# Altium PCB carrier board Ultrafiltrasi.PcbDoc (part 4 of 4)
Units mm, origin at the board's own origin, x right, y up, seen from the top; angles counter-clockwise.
Board outline 196.34 x 220.85 mm, 2 copper layers (Top Layer, Bottom Layer); 114 components, 209 nets, 667 pads, 70 vias.
Unrouted connection lines stored in the file: 5.
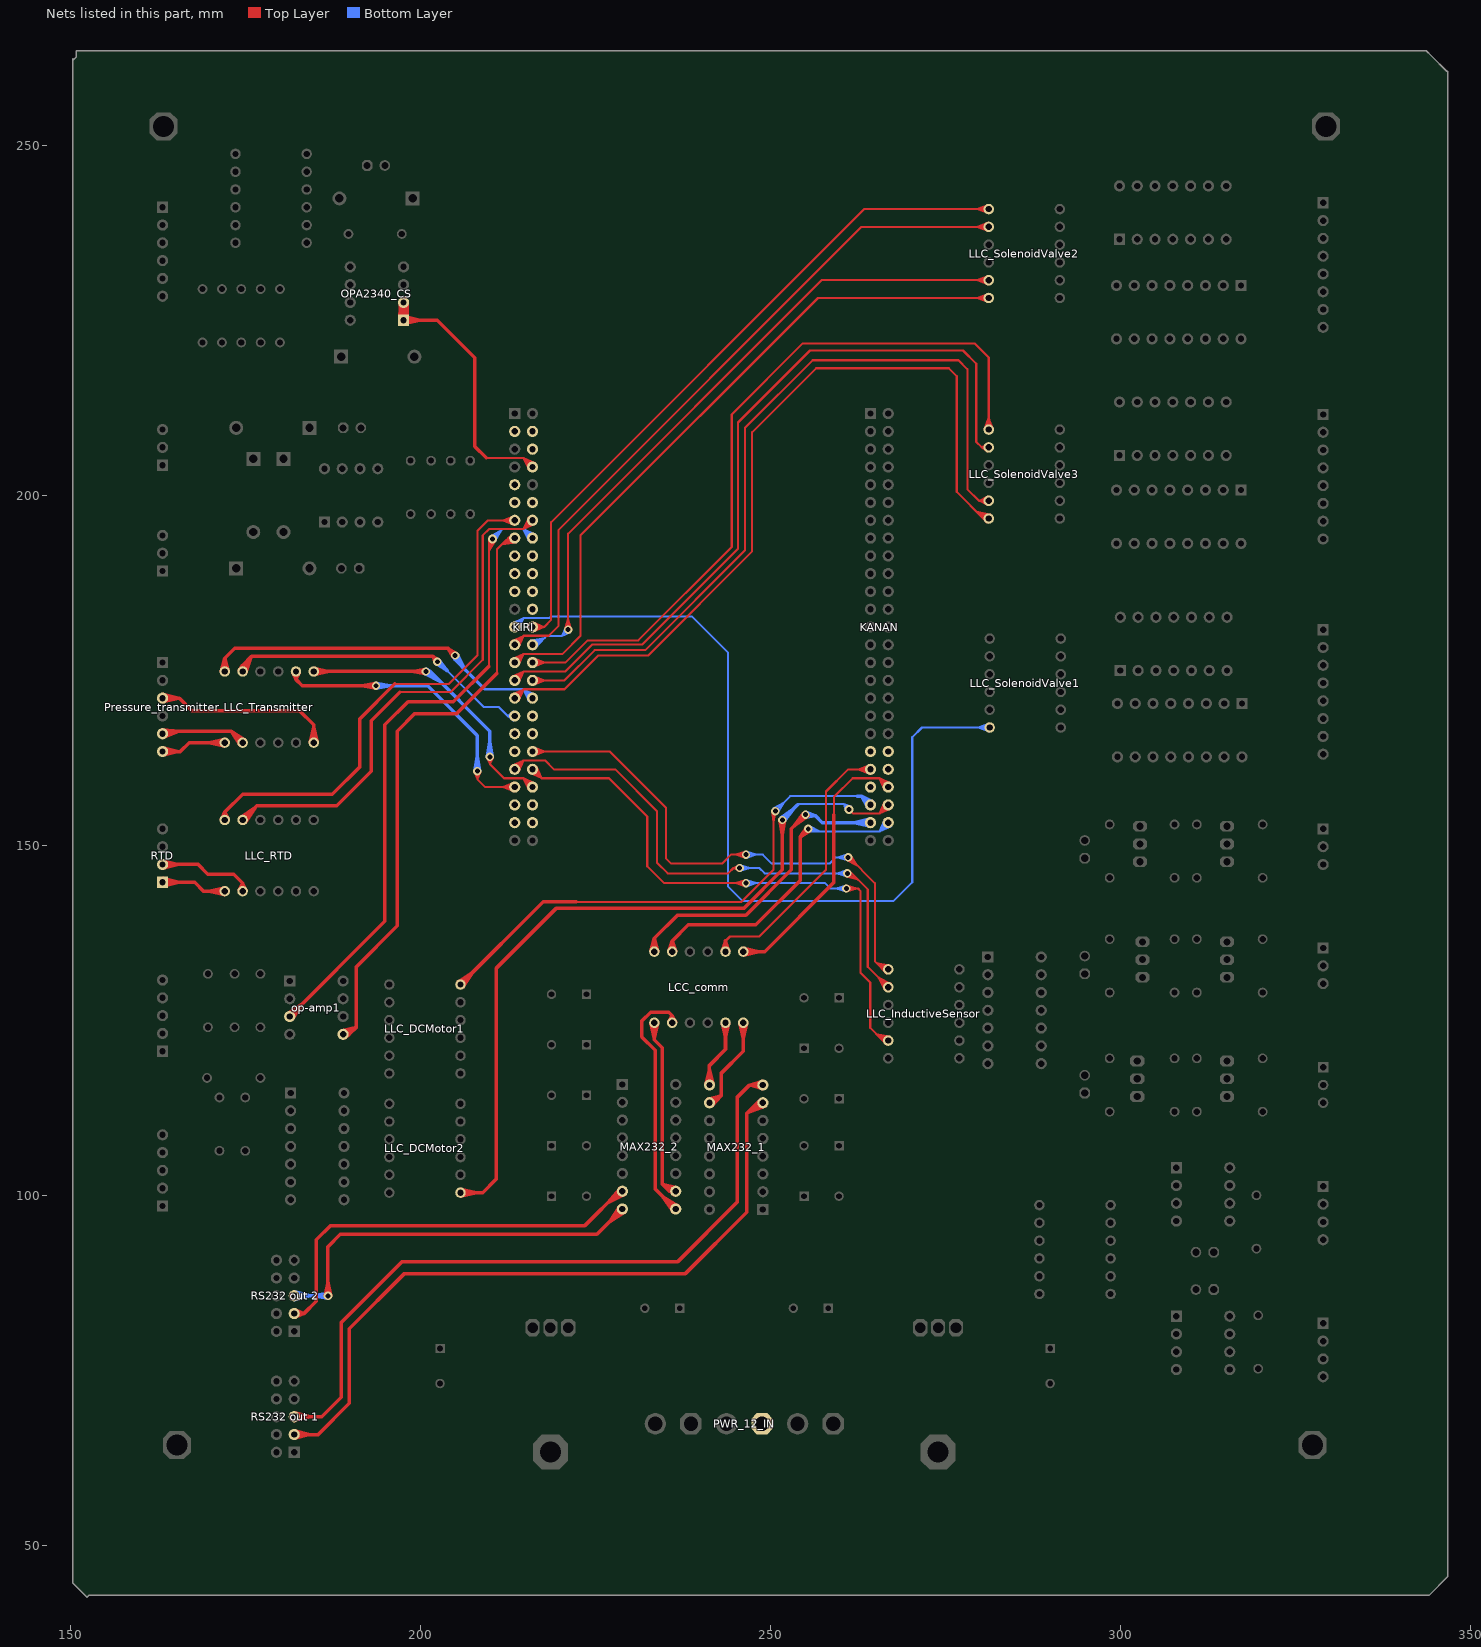
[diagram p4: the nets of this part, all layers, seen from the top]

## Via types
v1: diameter 1.2, hole 0.711, Top Layer to Bottom Layer, 26 vias
v2: diameter 1.27, hole 0.711, Top Layer to Bottom Layer, 24 vias
v3: diameter 1.2, hole 0.7, Top Layer to Bottom Layer, 19 vias
v4: diameter 1.5, hole 0.8, Top Layer to Bottom Layer, 1 vias

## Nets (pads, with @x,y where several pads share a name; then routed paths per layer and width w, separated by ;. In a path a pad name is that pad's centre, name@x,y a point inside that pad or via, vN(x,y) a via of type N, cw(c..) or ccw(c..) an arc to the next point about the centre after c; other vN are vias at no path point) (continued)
NetKANAN_39: KANAN.39
NetKANAN_40: KANAN.40
NetKANAN_41: KANAN.41 LCC_comm.P$2 | length 48.8
  Top Layer w0.3: 243.586,136.398 244.221,137.033 248.412,137.033 257.937,146.558 257.937,157.734 261.112,160.909 KANAN.41@264.287,160.909 ; KANAN.41@264.163,160.271 262.587,160.909 ; KANAN.41@264.163,161.547 262.587,160.909 ; KANAN.41@264.251,160.561 262.587,160.909 ; KANAN.41@264.251,161.257 262.587,160.909
  Top Layer w0.5: LCC_comm.P$2@243.093,134.956 243.586,136.398 ; LCC_comm.P$2@243.586,134.874 243.586,136.398 ; LCC_comm.P$2@244.079,134.956 243.586,136.398
NetKANAN_42: KANAN.42
NetKANAN_43: KANAN.43
NetKANAN_44: KANAN.44 LCC_comm.P$1 | length 52.1
  Top Layer w0.3: 259.08,154.432 259.08,156.972 261.747,159.639 265.557,159.639 ; KANAN.44@266.292,158 265.557,159.639 ; KANAN.44@266.557,158.147 265.557,159.639 ; KANAN.44@267.049,158.639 265.557,159.639 ; KANAN.44@267.196,158.904 265.557,159.639 ; 265.557,159.639 KANAN.44@266.827,158.369 265.557,159.639
  Top Layer w0.5: LCC_comm.P$1@246.126,134.874 249.174,134.874 259.08,144.78 259.08,154.432 ; LCC_comm.P$1@246.182,134.377 248.376,134.874 LCC_comm.P$1@246.182,135.371
NetKANAN_45: KANAN.45 LLC_DCMotor1.P$6 | length 92.1
  Top Layer w0.3: 222.25,141.986 245.872,141.986 250.444,146.558 250.444,154.686 v1(250.698,154.94) 250.444,153.367 v1@250.248,154.948
  Top Layer w0.5: LLC_DCMotor1.P$6@205.423,130.561 207.551,131.986 LLC_DCMotor1.P$6@206.126,129.858 ; LLC_DCMotor1.P$6@205.74,130.175 217.551,141.986 222.25,141.986
  Bottom Layer w0.3: v1@250.423,155.296 251.934,156.176 v1@251.054,154.665 ; v1(250.698,154.94) 252.837,157.079 262.382,157.079
  Bottom Layer w0.5: 262.382,157.079 263.037,157.079 ; KANAN.45@263.842,155.505 263.037,157.079 ; KANAN.45@264.611,156.274 263.037,157.079 ; 263.037,157.079 KANAN.45@264.287,155.829 263.037,157.079
NetKANAN_46: KANAN.46 LLC_DCMotor2.P$1 | length 135.6
  Top Layer w0.3: v2(261.239,155.194) 261.854,154.579 265.577,154.579 ; KANAN.46@266.291,156.196 265.577,154.579 ; KANAN.46@266.556,156.051 265.577,154.579 ; KANAN.46@267.049,155.558 265.577,154.579 ; KANAN.46@267.194,155.293 265.577,154.579 ; 265.577,154.579 KANAN.46@266.827,155.829 265.577,154.579
  Top Layer w0.5: LLC_DCMotor2.P$1@205.74,100.457 208.915,100.457 210.82,102.362 210.82,132.461 219.456,141.097 246.253,141.097 251.714,146.558 v3(251.714,153.67) 251.714,151.57 ; LLC_DCMotor2.P$1@205.796,99.96 207.99,100.457 LLC_DCMotor2.P$1@205.796,100.954 ; v3@251.365,153.641 251.714,151.57 ; v3@252.063,153.641 251.714,151.57
  Bottom Layer w0.3: 253.873,155.829 254,155.956 260.477,155.956 ; v2@260.828,154.937 260.477,155.956 ; v2@261.097,155.075 260.477,155.956 ; v2(261.239,155.194) 260.477,155.956 ; v2@261.358,155.336 260.477,155.956 ; v2@261.496,155.605 260.477,155.956
  Bottom Layer w0.5: v3@251.486,153.935 253.375,155.331 v3@251.979,153.442 ; v3(251.714,153.67) 253.873,155.829
NetKANAN_47: KANAN.47 LCC_comm.P$6 | length 63.9
  Top Layer w0.5: LCC_comm.P$6@232.93,134.94 233.426,136.779 ; LCC_comm.P$6@233.426,134.874 233.426,136.779 ; LCC_comm.P$6@233.922,134.94 233.426,136.779 ; v3@254.751,154.66 253.355,152.771 ; v3(255.016,154.432) 253.355,152.771 ; v3@255.244,154.167 253.355,152.771 ; v3@255.397,154.305 254.889,154.305 252.984,152.4 252.984,146.558 246.507,140.081 236.728,140.081 233.426,136.779
  Bottom Layer w0.5: v3@255.016,154.305 256.413,154.305 ; v3(255.016,154.432) 256.413,154.305 ; v3@255.028,154.082 256.413,154.305 ; v3@255.091,154.774 256.413,154.305 ; KANAN.47@264.221,152.743 261.987,153.289 KANAN.47@264.221,153.835 ; KANAN.47@264.287,153.289 257.429,153.289 256.413,154.305
NetKANAN_48: KANAN.48 LCC_comm.P$5 | length 65.5
  Top Layer w0.5: LCC_comm.P$5@235.473,134.956 235.966,136.398 ; LCC_comm.P$5@235.966,134.874 235.966,136.398 ; LCC_comm.P$5@236.459,134.956 235.966,136.398 ; v3@255.124,152.619 254.254,151.257 ; v3@255.27,152.273 254.254,151.257 ; v3@255.397,152.146 v3(255.397,152.4) 254.254,151.257 ; v3@255.616,152.127 254.254,151.257 ; 235.966,136.398 238.252,138.684 247.904,138.684 254.254,145.034 254.254,151.257
  Bottom Layer w0.3: v3@255.356,151.952 257.098,152.019 ; v3@255.551,152.823 257.098,152.019 ; KANAN.48@266.292,153.658 265.557,152.019 ; KANAN.48@266.557,153.511 265.557,152.019 ; KANAN.48@267.049,153.019 265.557,152.019 ; KANAN.48@267.196,152.754 265.557,152.019 ; 257.098,152.019 v3(255.397,152.4) 255.778,152.019 265.557,152.019 ; 265.557,152.019 KANAN.48@266.827,153.289 265.557,152.019
NetKIRI_3: KIRI.3 KIRI.4
NetKIRI_6: KIRI.6
NetKIRI_8: KIRI.8 OPA2340_CS.1 OPA2340_CS.2 | length 73.9
  Top Layer w0.3: 209.403,205.379 214.737,205.379 ; KIRI.8@215.493,203.719 214.737,205.379 ; KIRI.8@215.757,203.866 214.737,205.379 ; KIRI.8@216.25,204.359 214.737,205.379 ; KIRI.8@216.397,204.623 214.737,205.379 ; 214.737,205.379 KIRI.8@216.027,204.089 214.737,205.379
  Top Layer w0.5: OPA2340_CS.1@197.065,224.991 OPA2340_CS.2@197.116,227.311 ; OPA2340_CS.1@197.066,225.11 197.612,227.344 OPA2340_CS.1@198.158,225.11 ; OPA2340_CS.2@197.066,227.518 197.612,225.284 OPA2340_CS.2@198.158,227.518 ; OPA2340_CS.1@197.092,225.224 OPA2340_CS.2@198.108,227.311 ; OPA2340_CS.2@197.612,227.584 OPA2340_CS.1@197.612,225.044 ; OPA2340_CS.1@197.678,224.498 199.912,225.044 OPA2340_CS.1@197.678,225.59 ; OPA2340_CS.1@198.132,225.224 OPA2340_CS.2@197.116,227.311 ; OPA2340_CS.1@198.159,224.991 OPA2340_CS.2@198.108,227.311 ; 209.403,205.379 207.772,207.01 207.772,219.71 202.438,225.044 OPA2340_CS.1@197.612,225.044 ; OPA2340_CS.2@197.116,227.311 OPA2340_CS.1@197.612,225.044 ; OPA2340_CS.1@197.612,225.044 OPA2340_CS.2@198.108,227.311
NetKIRI_9: KIRI.9
NetKIRI_11: KIRI.11
NetKIRI_12: KIRI.12
NetKIRI_13: KIRI.13 LLC_RTD.P$6 | length 83.3
  Top Layer w0.3: 196.342,173.101 204.089,173.101 208.153,177.165 208.153,194.945 209.677,196.469 KIRI.13@213.487,196.469 ; KIRI.13@213.363,195.831 211.787,196.469 ; KIRI.13@213.363,197.107 211.787,196.469 ; KIRI.13@213.451,196.121 211.787,196.469 ; KIRI.13@213.451,196.817 211.787,196.469
  Top Layer w0.5: LLC_RTD.P$6@171.597,153.779 172.085,154.813 ; LLC_RTD.P$6@172.085,153.67 172.085,154.813 ; LLC_RTD.P$6@172.573,153.779 172.085,154.813 ; 196.342,173.101 191.389,168.148 191.389,161.29 187.452,157.353 174.625,157.353 172.085,154.813
NetKIRI_14: KIRI.14 LLC_RTD.P$5 | length 87.9
  Top Layer w0.3: 197.04,171.958 204.343,171.958 208.915,176.53 208.915,194.31 209.804,195.199 214.757,195.199 ; KIRI.14@215.492,196.838 214.757,195.199 ; KIRI.14@215.757,196.691 214.757,195.199 ; KIRI.14@216.249,196.199 214.757,195.199 ; KIRI.14@216.396,195.934 214.757,195.199 ; 214.757,195.199 KIRI.14@216.027,196.469 214.757,195.199
  Top Layer w0.5: LLC_RTD.P$5@174.308,154.056 176.436,155.481 LLC_RTD.P$5@175.011,153.353 ; LLC_RTD.P$5@174.625,153.67 176.657,155.702 188.087,155.702 192.992,160.607 192.992,167.846 197.04,171.894
NetKIRI_15: KIRI.15 op-amp1.5 | length 115.1
  Top Layer w0.3: 210.947,174.625 210.947,192.318 212.558,193.929 ; KIRI.15@213.111,194.459 211.659,193.03 ; KIRI.15@213.306,194.229 211.659,193.03 ; KIRI.15@213.614,193.603 211.659,193.03 ; KIRI.15@213.677,193.307 211.659,193.03 ; 211.659,193.03 KIRI.15@213.487,193.929 ; 212.558,193.929 KIRI.15@213.487,193.929 ; 212.558,193.929 213.421,194.273 212.558,193.929 ; 212.558,193.929 213.421,193.585 212.558,193.929 ; 212.558,193.929 213.26,194.538 212.558,193.929 ; 212.558,193.929 213.26,193.32 212.558,193.929 ; 212.558,193.929 KIRI.15@213.487,193.929
  Top Layer w0.5: op-amp1.5@188.781,123.577 190.881,124.079 ; op-amp1.5@189.295,122.615 190.881,124.079 ; 210.947,174.625 205.2,168.878 199.231,168.878 196.723,166.37 196.723,138.557 190.881,132.715 190.881,124.079 ; op-amp1.5@188.976,123.063 189.865,123.063 ; op-amp1.5@188.976,123.063 190.881,124.079 ; op-amp1.5@188.976,123.063 189.865,123.063 ; 189.865,123.063 189.146,122.54 189.865,123.063 ; 189.865,123.063 189.146,123.586 189.865,123.063 ; 189.865,123.063 190.881,124.079
NetKIRI_16: KIRI.16 op-amp1.3 | length 121.2
  Top Layer w0.3: 209.804,175.641 209.804,193.294 v2(210.312,193.802) 209.804,192.1 ; v2@209.833,193.876 209.804,192.1 ; v2@210.132,193.846 209.804,192.1 ; v2@210.486,193.74 209.804,192.1 ; v2@210.753,193.601 209.804,192.1 ; KIRI.16@215.987,193.929 KIRI.16@216.027,193.929
  Top Layer w0.5: op-amp1.3@181.01,126.03 183.217,127.464 op-amp1.3@181.783,125.257 ; op-amp1.3@181.356,125.603 194.945,139.192 194.945,167.259 198.247,170.561 204.724,170.561 209.804,175.641
  Bottom Layer w0.3: v2@210.018,194.188 211.583,195.073 ; v2@210.188,193.939 211.583,195.073 ; v2(210.312,193.802) 211.709,195.199 214.757,195.199 ; v2@210.449,193.678 211.583,195.073 ; v2@210.698,193.508 211.583,195.073 ; KIRI.16@215.492,193.56 214.757,195.199 ; KIRI.16@215.757,193.707 214.757,195.199 ; KIRI.16@216.249,194.199 214.757,195.199 ; KIRI.16@216.396,194.464 214.757,195.199 ; 214.757,195.199 KIRI.16@216.027,193.929 214.757,195.199
NetKIRI_17: KIRI.17
NetKIRI_18: KIRI.18
NetKIRI_19: KIRI.19
NetKIRI_20: KIRI.20
NetKIRI_21: KIRI.21
NetKIRI_22: KIRI.22
NetKIRI_24: KIRI.24
NetKIRI_25: KIRI.25 LLC_SolenoidValve1.P$6 | length 141.1
  Bottom Layer w0.3: KIRI.25@213.117,181.763 214.777,182.519 ; KIRI.25@213.264,181.499 214.777,182.519 ; KIRI.25@213.487,181.229 214.777,182.519 ; KIRI.25@213.757,181.006 214.777,182.519 ; KIRI.25@214.021,180.859 214.777,182.519 ; LLC_SolenoidValve1.P$6@281.196,166.288 279.655,166.878 ; LLC_SolenoidValve1.P$6@281.196,167.468 279.655,166.878 ; LLC_SolenoidValve1.P$6@281.278,166.579 279.655,166.878 ; LLC_SolenoidValve1.P$6@281.278,167.177 279.655,166.878 ; LLC_SolenoidValve1.P$6@281.305,166.878 271.653,166.878 270.256,165.481 270.256,144.78 267.589,142.113 245.999,142.113 243.967,144.145 243.967,177.546 238.76,182.753 218.694,182.753 218.46,182.519 214.777,182.519
NetKIRI_26: KIRI.26 LLC_SolenoidValve2.P$1 | length 111.3
  Top Layer w0.3: KIRI.26@216.027,181.229 217.678,181.229 ; KIRI.26@216.064,180.881 217.678,181.229 ; KIRI.26@216.064,181.577 217.678,181.229 ; KIRI.26@216.155,180.592 217.678,181.229 ; KIRI.26@216.155,181.866 217.678,181.229 ; LLC_SolenoidValve2.P$1@281.069,240.329 279.528,240.919 ; LLC_SolenoidValve2.P$1@281.069,241.509 279.528,240.919 ; LLC_SolenoidValve2.P$1@281.151,240.62 279.528,240.919 ; LLC_SolenoidValve2.P$1@281.151,241.218 279.528,240.919 ; LLC_SolenoidValve2.P$1@281.178,240.919 263.398,240.919 218.694,196.215 218.694,182.245 217.678,181.229
NetKIRI_27: KIRI.27 LLC_SolenoidValve2.P$2 | length 114.3
  Top Layer w0.3: KIRI.27@213.117,179.223 214.777,179.979 ; KIRI.27@213.264,178.959 214.777,179.979 ; KIRI.27@213.487,178.689 214.777,179.979 ; KIRI.27@213.757,178.466 214.777,179.979 ; KIRI.27@214.021,178.319 214.777,179.979 ; LLC_SolenoidValve2.P$2@281.069,237.789 279.528,238.379 ; LLC_SolenoidValve2.P$2@281.069,238.969 279.528,238.379 ; LLC_SolenoidValve2.P$2@281.151,238.08 279.528,238.379 ; LLC_SolenoidValve2.P$2@281.151,238.678 279.528,238.379 ; LLC_SolenoidValve2.P$2@281.178,238.379 263.017,238.379 219.71,195.072 219.71,181.356 218.333,179.979 214.777,179.979
NetKIRI_28: KIRI.28 LLC_SolenoidValve2.P$5 | length 116.9
  Top Layer w0.3: v1@220.662,180.916 221.107,182.348 v1@221.552,180.916 ; v1(221.107,180.848) 221.107,194.564 257.302,230.759 LLC_SolenoidValve2.P$5@281.178,230.759 ; LLC_SolenoidValve2.P$5@281.069,230.169 279.528,230.759 ; LLC_SolenoidValve2.P$5@281.069,231.349 279.528,230.759 ; LLC_SolenoidValve2.P$5@281.151,230.46 279.528,230.759 ; LLC_SolenoidValve2.P$5@281.151,231.058 279.528,230.759
  Bottom Layer w0.3: KIRI.28@215.803,179.299 217.78,179.68 ; KIRI.28@215.882,179.008 217.78,179.68 ; KIRI.28@216.225,178.4 217.78,179.68 ; KIRI.28@216.434,178.182 217.78,179.68 ; v1@220.737,181.104 220.218,179.959 ; v1(221.107,180.848) 220.218,179.959 ; v1@221.363,180.478 220.218,179.959 ; 217.78,179.68 KIRI.28@216.027,178.689 216.789,178.689 218.059,179.959 220.218,179.959
NetKIRI_29: KIRI.29 LLC_SolenoidValve2.P$6 | length 111.3
  Top Layer w0.3: KIRI.29@213.12,176.685 214.737,177.399 ; KIRI.29@213.265,176.42 214.737,177.399 ; KIRI.29@213.487,176.149 214.737,177.399 ; KIRI.29@213.758,175.927 214.737,177.399 ; KIRI.29@214.023,175.782 214.737,177.399 ; LLC_SolenoidValve2.P$6@281.069,227.629 279.528,228.219 ; LLC_SolenoidValve2.P$6@281.069,228.809 279.528,228.219 ; LLC_SolenoidValve2.P$6@281.151,227.92 279.528,228.219 ; LLC_SolenoidValve2.P$6@281.151,228.518 279.528,228.219 ; LLC_SolenoidValve2.P$6@281.178,228.219 256.794,228.219 222.885,194.31 222.885,179.959 220.325,177.399 214.737,177.399
NetKIRI_30: KIRI.30 LLC_SolenoidValve3.P$1 | length 119.6
  Top Layer w0.3: KIRI.30@216.027,176.149 220.726,176.149 223.901,179.324 231.14,179.324 244.475,192.659 244.475,211.582 254.635,221.742 279.146,221.742 281.178,219.71 LLC_SolenoidValve3.P$1@281.178,209.423 ; KIRI.30@216.063,175.801 217.727,176.149 ; KIRI.30@216.063,176.497 217.727,176.149 ; KIRI.30@216.151,175.511 217.727,176.149 ; KIRI.30@216.151,176.787 217.727,176.149 ; LLC_SolenoidValve3.P$1@280.588,209.532 281.178,211.073 ; LLC_SolenoidValve3.P$1@280.879,209.45 281.178,211.073 ; LLC_SolenoidValve3.P$1@281.477,209.45 281.178,211.073 ; LLC_SolenoidValve3.P$1@281.768,209.532 281.178,211.073
NetKIRI_31: KIRI.31 LLC_SolenoidValve3.P$2 | length 121.3
  Top Layer w0.3: KIRI.31@213.118,174.144 214.757,174.879 ; KIRI.31@213.265,173.879 214.757,174.879 ; KIRI.31@213.487,173.609 214.757,174.879 ; KIRI.31@213.757,173.387 214.757,174.879 ; KIRI.31@214.022,173.24 214.757,174.879 ; LLC_SolenoidValve3.P$2@281.001,206.31 280.162,206.883 ; LLC_SolenoidValve3.P$2@281.001,207.456 280.162,206.883 ; LLC_SolenoidValve3.P$2@281.134,206.586 280.162,206.883 ; LLC_SolenoidValve3.P$2@281.134,207.18 280.162,206.883 ; LLC_SolenoidValve3.P$2@281.178,206.883 280.162,206.883 ; 214.757,174.879 220.686,174.879 224.531,178.724 231.683,178.724 245.364,192.405 245.364,210.439 255.651,220.726 277.495,220.726 279.4,218.821 279.4,207.645 280.162,206.883
NetKIRI_32: KIRI.32 LLC_SolenoidValve3.P$5 | length 126.5
  Top Layer w0.3: KIRI.32@216.027,173.609 220.599,173.609 224.917,177.927 232.116,177.927 246.38,192.191 246.38,209.677 256.032,219.329 276.86,219.329 278.13,218.059 278.13,200.914 279.781,199.263 ; KIRI.32@216.063,173.261 217.727,173.609 ; KIRI.32@216.063,173.957 217.727,173.609 ; KIRI.32@216.151,172.971 217.727,173.609 ; KIRI.32@216.151,174.247 217.727,173.609 ; LLC_SolenoidValve3.P$5@281.049,198.677 279.781,199.263 ; LLC_SolenoidValve3.P$5@281.049,199.849 279.781,199.263 ; LLC_SolenoidValve3.P$5@281.146,198.965 279.781,199.263 ; LLC_SolenoidValve3.P$5@281.146,199.561 279.781,199.263 ; 279.781,199.263 LLC_SolenoidValve3.P$5@281.178,199.263 279.781,199.263
NetKIRI_33: KIRI.33 LLC_SolenoidValve3.P$6 | length 140
  Top Layer w0.3: KIRI.33@213.118,171.604 214.757,172.339 ; KIRI.33@213.265,171.339 214.757,172.339 ; KIRI.33@213.487,171.069 214.757,172.339 ; KIRI.33@213.757,170.847 214.757,172.339 ; KIRI.33@214.022,170.7 214.757,172.339 ; LLC_SolenoidValve3.P$6@280.807,196.251 279.403,197.736 ; LLC_SolenoidValve3.P$6@281.011,196.474 279.403,197.736 ; LLC_SolenoidValve3.P$6@281.307,196.994 279.403,197.736 ; LLC_SolenoidValve3.P$6@281.396,197.282 279.403,197.736 ; 214.757,172.339 220.599,172.339 225.425,177.165 232.537,177.165 247.396,192.024 247.396,209.042 256.54,218.186 275.463,218.186 276.606,217.043 276.606,200.533 280.416,196.723 ; 279.403,197.736 LLC_SolenoidValve3.P$6@281.178,196.723 ; 280.416,196.723 LLC_SolenoidValve3.P$6@281.178,196.723 ; 280.416,196.723 281.119,197.017 280.416,196.723 ; 280.416,196.723 281.119,196.429 280.416,196.723 ; 280.416,196.723 280.942,197.275 280.416,196.723 ; 280.416,196.723 280.942,196.171 280.416,196.723 ; 280.416,196.723 LLC_SolenoidValve3.P$6@281.178,196.723
NetKIRI_34: KIRI.34 LLC_Transmitter.P$6 | length 77.3
  Top Layer w0.5: LLC_Transmitter.P$6@171.589,174.945 172.085,176.784 ; LLC_Transmitter.P$6@172.085,174.879 172.085,176.784 ; LLC_Transmitter.P$6@172.581,174.945 172.085,176.784 ; v3@204.702,176.949 203.962,178.181 ; v3@205.194,177.441 203.962,178.181 ; 172.085,176.784 173.482,178.181 203.962,178.181 ; 203.962,178.181 v3(204.978,177.165) 203.962,178.181
  Bottom Layer w0.3: 209.042,172.466 209.169,172.339 214.757,172.339 ; KIRI.34@215.492,170.7 214.757,172.339 ; KIRI.34@215.757,170.847 214.757,172.339 ; KIRI.34@216.249,171.339 214.757,172.339 ; KIRI.34@216.396,171.604 214.757,172.339 ; 214.757,172.339 KIRI.34@216.027,171.069 214.757,172.339
  Bottom Layer w0.5: v3@204.704,176.947 206.345,175.163 ; v3@205.281,177.341 206.345,175.163 ; 209.042,172.466 204.978,176.53 ; 204.978,176.53 v3(204.978,177.165) ; 204.978,176.53 204.642,177.069 204.978,176.53 ; 204.978,176.53 205.314,177.069 204.978,176.53 ; 204.978,176.53 v3(204.978,177.165) ; v3(204.978,177.165) 206.345,175.163
NetKIRI_35: KIRI.35 LLC_Transmitter.P$5 | length 68.5
  Top Layer w0.5: LLC_Transmitter.P$5@174.221,175.174 175.895,177.038 ; LLC_Transmitter.P$5@175.079,174.67 175.895,177.038 ; v3@202.134,176.103 201.803,177.038 ; v3(202.438,176.276) 201.803,177.038 ; v3@202.438,176.403 201.803,177.038 ; v3@202.663,176.544 201.803,177.038 ; LLC_Transmitter.P$5@174.625,174.879 174.625,175.768 ; LLC_Transmitter.P$5@174.625,174.879 175.895,177.038 ; LLC_Transmitter.P$5@174.625,174.879 174.625,175.768 ; 174.625,175.768 175.105,175.02 174.625,175.768 ; 174.625,175.768 174.145,175.02 174.625,175.768 ; 174.625,175.768 175.895,177.038 ; 175.895,177.038 201.803,177.038
  Bottom Layer w0.3: 203.835,175.006 209.042,169.799 211.201,169.799 212.471,168.529 ; KIRI.35@213.279,167.913 212.471,168.529 ; KIRI.35@213.279,169.145 212.471,168.529 ; KIRI.35@213.427,168.184 212.471,168.529 ; KIRI.35@213.427,168.874 212.471,168.529 ; KIRI.35@213.487,168.529 212.471,168.529
  Bottom Layer w0.5: v3@202.228,175.996 203.835,175.006 ; v3(202.438,176.276) 203.835,175.006 ; v3@202.438,176.403 203.835,175.006 ; v3@202.696,176.512 203.835,175.006
NetKIRI_36: KIRI.36
NetKIRI_37: KIRI.37
NetKIRI_38: KIRI.38
NetKIRI_39: KIRI.39
NetKIRI_40: KIRI.40 LLC_InductiveSensor.P$1 | length 114.3
  Top Layer w0.3: KIRI.40@216.027,163.449 227.076,163.449 235.077,155.448 235.077,148.209 235.839,147.447 243.078,147.447 244.348,148.717 v1(246.507,148.717) ; KIRI.40@216.063,163.101 217.727,163.449 ; KIRI.40@216.063,163.797 217.727,163.449 ; KIRI.40@216.151,162.811 217.727,163.449 ; KIRI.40@216.151,164.087 217.727,163.449 ; v1@246.439,148.272 245.007,148.717 v1@246.439,149.162 ; v1@260.856,147.966 262.404,147.171 ; v1(261.112,148.336) 262.404,147.171 ; v1@261.175,148.399 264.922,144.653 264.922,133.477 266.065,132.334 ; v1@261.454,148.628 262.404,147.171 ; LLC_InductiveSensor.P$1@266.461,131.858 265.167,133.232 ; LLC_InductiveSensor.P$1@266.664,132.082 265.167,133.232 ; LLC_InductiveSensor.P$1@266.948,132.608 265.167,133.232 ; LLC_InductiveSensor.P$1@267.025,132.9 265.167,133.232 ; 265.167,133.232 LLC_InductiveSensor.P$1@266.827,132.334 ; 266.065,132.334 LLC_InductiveSensor.P$1@266.827,132.334 ; 266.065,132.334 266.768,132.628 266.065,132.334 ; 266.065,132.334 266.768,132.04 266.065,132.334 ; 266.065,132.334 266.591,132.886 266.065,132.334 ; 266.065,132.334 266.591,131.782 266.065,132.334 ; 266.065,132.334 LLC_InductiveSensor.P$1@266.827,132.334 ; 266.065,132.334 LLC_InductiveSensor.P$1@266.827,132.334
  Bottom Layer w0.3: v1(246.507,148.717) 248.92,148.717 250.19,147.447 258.445,147.447 259.334,148.336 v1(261.112,148.336) ; v1@246.575,148.272 248.007,148.717 v1@246.575,149.162 ; v1@261.044,147.891 259.612,148.336 v1@261.044,148.781
NetKIRI_41: KIRI.41 LLC_InductiveSensor.P$2 | length 112.9
  Top Layer w0.3: KIRI.41@213.118,161.444 214.757,162.179 ; KIRI.41@213.265,161.179 214.757,162.179 ; KIRI.41@213.487,160.909 214.757,162.179 ; KIRI.41@213.757,160.687 214.757,162.179 ; KIRI.41@214.022,160.54 214.757,162.179 ; v1@245.504,146.377 244.729,146.812 ; v1@245.504,147.247 244.729,146.812 ; v1@260.807,145.637 262.53,145.14 ; v1@261.26,146.406 262.53,145.14 ; LLC_InductiveSensor.P$2@266.343,129.44 265.441,131.18 ; LLC_InductiveSensor.P$2@266.599,129.599 265.441,131.18 ; LLC_InductiveSensor.P$2@267.022,130.022 265.441,131.18 ; LLC_InductiveSensor.P$2@267.181,130.278 265.441,131.18 ; 214.757,162.179 217.805,162.179 219.075,160.909 227.838,160.909 233.807,154.94 233.807,147.574 235.331,146.05 243.967,146.05 244.729,146.812 ; 244.729,146.812 v1(245.618,146.812) 244.729,146.812 ; v1(260.985,146.05) 261.62,146.05 ; v1(260.985,146.05) 262.53,145.14 ; v1(260.985,146.05) 261.62,146.05 ; 261.62,146.05 261.144,145.629 261.62,146.05 ; 261.62,146.05 261.144,146.471 261.62,146.05 ; 261.62,146.05 263.906,143.764 263.906,132.715 LLC_InductiveSensor.P$2@266.827,129.794 265.441,131.18
  Bottom Layer w0.3: v1(245.618,146.812) 248.412,146.812 249.174,146.05 v1(260.985,146.05) ; v1@245.686,146.367 247.118,146.812 v1@245.686,147.257 ; v1@260.917,145.605 259.485,146.05 v1@260.917,146.495
NetKIRI_42: KIRI.42 LLC_InductiveSensor.P$5 | length 119
  Top Layer w0.3: KIRI.42@215.658,160.374 217.297,159.639 ; KIRI.42@215.805,160.639 217.297,159.639 ; KIRI.42@216.027,160.909 217.297,159.639 ; KIRI.42@216.297,161.131 217.297,159.639 ; KIRI.42@216.562,161.278 217.297,159.639 ; v1@246.439,144.208 245.007,144.653 ; v1@246.439,145.098 245.007,144.653 ; v1(260.858,143.891) 262.509,143.891 262.89,143.51 262.89,131.826 264.255,130.461 264.255,123.984 266.065,122.174 ; v1@260.926,143.446 262.358,143.891 v1@260.926,144.336 ; LLC_InductiveSensor.P$5@266.459,121.7 265.116,123.123 ; LLC_InductiveSensor.P$5@266.662,121.924 265.116,123.123 ; LLC_InductiveSensor.P$5@266.952,122.447 265.116,123.123 ; LLC_InductiveSensor.P$5@267.034,122.737 265.116,123.123 ; 217.297,159.639 226.949,159.639 232.41,154.178 232.41,147.066 234.823,144.653 v1(246.507,144.653) 245.007,144.653 ; 265.116,123.123 LLC_InductiveSensor.P$5@266.827,122.174 ; 266.065,122.174 LLC_InductiveSensor.P$5@266.827,122.174 ; 266.065,122.174 266.768,122.468 266.065,122.174 ; 266.065,122.174 266.768,121.88 266.065,122.174 ; 266.065,122.174 266.591,122.726 266.065,122.174 ; 266.065,122.174 266.591,121.622 266.065,122.174 ; 266.065,122.174 LLC_InductiveSensor.P$5@266.827,122.174
  Bottom Layer w0.3: v1(246.507,144.653) 257.81,144.653 258.572,143.891 v1(260.858,143.891) ; v1@246.575,144.208 248.007,144.653 v1@246.575,145.098 ; v1@260.79,143.446 259.358,143.891 v1@260.79,144.336
NetKIRI_43: KIRI.43 LLC_Transmitter.P$2 | length 68.5
  Top Layer w0.3: v1@207.712,160.566 208.153,159.512 ; v1(208.153,160.655) 208.153,159.512 ; v1@208.594,160.566 208.153,159.512 ; KIRI.43@213.363,157.731 211.787,158.369 ; KIRI.43@213.363,159.007 211.787,158.369 ; KIRI.43@213.451,158.021 211.787,158.369 ; KIRI.43@213.451,158.717 211.787,158.369 ; KIRI.43@213.487,158.369 209.296,158.369 208.153,159.512
  Top Layer w0.5: LLC_Transmitter.P$2@181.757,174.77 182.245,173.736 ; LLC_Transmitter.P$2@182.245,174.879 182.245,173.736 ; LLC_Transmitter.P$2@182.733,174.77 182.245,173.736 ; v3@193.646,172.498 191.575,172.847 ; v3@193.646,173.196 191.575,172.847 ; 182.245,173.736 183.134,172.847 v3(193.675,172.847) 191.575,172.847
  Bottom Layer w0.5: v3(193.675,172.847) 201.041,172.847 208.153,165.735 v1(208.153,160.655) ; v3@193.704,172.498 195.775,172.847 v3@193.704,173.196 ; v1@207.804,160.684 208.153,162.755 v1@208.502,160.684
NetKIRI_44: KIRI.44 LLC_Transmitter.P$1 | length 75.3
  Top Layer w0.3: v1@209.492,162.587 209.931,161.671 ; v1(209.931,162.687) 209.931,161.671 ; v1@210.37,162.587 209.931,161.671 ; KIRI.44@215.492,158 214.757,159.639 ; KIRI.44@215.757,158.147 214.757,159.639 ; KIRI.44@216.249,158.639 214.757,159.639 ; KIRI.44@216.396,158.904 214.757,159.639 ; 209.931,161.671 211.963,159.639 214.757,159.639 ; 214.757,159.639 KIRI.44@216.027,158.369 214.757,159.639
  Top Layer w0.5: LLC_Transmitter.P$1@184.785,174.879 v3(200.787,174.879) ; LLC_Transmitter.P$1@184.841,174.382 187.035,174.879 LLC_Transmitter.P$1@184.841,175.376 ; v3@200.758,174.53 198.687,174.879 v3@200.758,175.228
  Bottom Layer w0.5: v3@200.61,174.577 202.816,173.485 ; v3@201.005,175.153 202.816,173.485 ; v1@209.582,162.716 209.931,164.787 v1@210.28,162.716 ; v1(209.931,162.687) 209.931,166.37 201.422,174.879 ; v3(200.787,174.879) 201.422,174.879 ; v3(200.787,174.879) 202.816,173.485 ; v3(200.787,174.879) 201.422,174.879 ; 201.422,174.879 200.883,174.543 201.422,174.879 ; 201.422,174.879 200.883,175.215 201.422,174.879
NetKIRI_45: KIRI.45
NetKIRI_46: KIRI.46
NetKIRI_47: KIRI.47
NetKIRI_48: KIRI.48
NetLCC_comm_P$7: LCC_comm.P$7 MAX232_2.10 | length 40.9
  Top Layer w0.5: LCC_comm.P$7@232.929,124.658 233.426,122.464 ; LCC_comm.P$7@233.923,124.658 233.426,122.464 ; MAX232_2.10@236.155,100.204 234.569,101.668 ; MAX232_2.10@236.304,100.129 235.585,100.652 ; MAX232_2.10@236.304,101.175 235.585,100.652 ; MAX232_2.10@236.669,101.166 234.569,101.668 ; 233.426,122.464 LCC_comm.P$7@233.426,124.714 233.426,122.301 234.569,121.158 234.569,101.668 ; 234.569,101.668 MAX232_2.10@236.474,100.652 235.585,100.652 ; 234.569,101.668 235.585,100.652
NetLCC_comm_P$8: LCC_comm.P$8 MAX232_2.9 | length 44.9
  Top Layer w0.5: LCC_comm.P$8@235.481,124.837 235.966,125.73 ; LCC_comm.P$8@235.966,124.714 235.966,125.73 ; MAX232_2.9@236.053,97.758 234.588,99.93 ; LCC_comm.P$8@236.451,124.837 235.966,125.73 ; MAX232_2.9@236.812,98.546 234.588,99.93 ; 234.588,99.93 MAX232_2.9@236.474,98.112 236.406,98.112 233.553,100.965 233.553,120.777 231.648,122.682 231.648,124.968 232.918,126.238 235.458,126.238 235.966,125.73
NetLCC_comm_P$11: LCC_comm.P$11 MAX232_1.9 | length 18.9
  Top Layer w0.5: MAX232_1.9@240.754,115.89 241.3,118.124 MAX232_1.9@241.846,115.89 ; MAX232_1.9@241.3,115.824 241.3,118.618 243.586,120.904 LCC_comm.P$11@243.586,124.714 ; LCC_comm.P$11@243.089,124.658 243.586,122.464 LCC_comm.P$11@244.083,124.658
NetLCC_comm_P$12: LCC_comm.P$12 MAX232_1.10 | length 24.1
  Top Layer w0.5: MAX232_1.10@241.081,113.789 242.951,114.3 ; MAX232_1.10@241.652,112.861 242.951,114.3 ; LCC_comm.P$12@245.629,124.658 246.126,122.464 LCC_comm.P$12@246.623,124.658 ; LCC_comm.P$12@246.126,124.714 246.126,120.65 242.951,117.475 242.951,114.3 ; 242.951,114.3 MAX232_1.10@241.3,113.284 241.935,113.284 242.951,114.3
NetLLC_Transmitter_P$12: LLC_Transmitter.P$12 Pressure_transmitter.3 | length 34.8
  Top Layer w0.5: Pressure_transmitter.3@163.195,171.069 165.608,171.069 167.386,169.291 182.753,169.291 184.785,167.259 LLC_Transmitter.P$12@184.785,164.719 ; Pressure_transmitter.3@163.261,170.523 165.495,171.069 Pressure_transmitter.3@163.261,171.615 ; LLC_Transmitter.P$12@184.288,164.775 184.785,166.969 LLC_Transmitter.P$12@185.282,164.775
NetMAX232_1_7: "RS232 out 1.3" MAX232_1.7 | length 113.5
  Top Layer w0.5: 181.991,65.913 185.42,65.913 189.865,70.358 189.865,81.026 197.739,88.9 237.871,88.9 246.634,97.663 246.634,111.76 248.158,113.284 MAX232_1.7@248.92,113.284 246.719,111.845 ; 182.057,65.367 184.291,65.913 182.057,66.459 ; MAX232_1.7@248.573,113.71 246.719,111.845 ; MAX232_1.7@249.171,112.795 246.719,111.845
NetMAX232_1_8: "RS232 out 1.5" MAX232_1.8 | length 111.9
  Top Layer w0.5: 181.991,68.453 185.928,68.453 188.722,71.247 188.722,81.915 197.358,90.551 236.728,90.551 245.237,99.06 245.237,114.046 247.015,115.824 ; 182.057,67.907 184.291,68.453 182.057,68.999 ; MAX232_1.8@248.841,115.28 247.015,115.824 ; MAX232_1.8@248.841,116.368 247.015,115.824 ; 247.015,115.824 MAX232_1.8@248.92,115.824 247.015,115.824
NetMAX232_2_7: "RS232 out 2.3" MAX232_2.7 | length 70
  Top Layer w0.5: 181.991,83.185 183.388,83.185 ; 182.099,82.646 183.388,83.185 ; 182.099,83.724 183.388,83.185 ; MAX232_2.7@228.47,101.046 226.775,99.013 ; MAX232_2.7@229.148,100.187 226.775,99.013 ; 183.388,83.185 185.166,84.963 185.166,93.726 187.198,95.758 223.52,95.758 228.414,100.652 MAX232_2.7@228.854,100.652 226.775,99.013
NetMAX232_2_8: "RS232 out 2.5" MAX232_2.8 | length 77.1
  Top Layer w0.5: v2@186.434,85.76 186.817,87.86 v2@187.2,85.76 ; v2(186.817,85.725) 186.817,92.71 188.595,94.488 225.23,94.488 MAX232_2.8@228.854,98.112 226.993,96.251 ; MAX232_2.8@228.427,98.458 226.993,96.251 ; MAX232_2.8@229.2,97.685 226.993,96.251
  Bottom Layer w0.5: 181.991,85.725 v2(186.817,85.725) ; 182.057,85.179 184.291,85.725 182.057,86.271 ; v2@186.782,85.342 184.682,85.725 v2@186.782,86.108
NetPWR_12_IN_1: PWR_12_IN.1
NRX: LLC_RTD.P$8 RTD.2 | length 20.6
  Top Layer w0.5: RTD.2@163.195,147.32 168.275,147.32 169.672,145.923 173.355,145.923 174.625,144.653 ; RTD.2@163.261,146.774 165.495,147.32 RTD.2@163.261,147.866 ; LLC_RTD.P$8@174.137,143.619 174.625,144.653 ; LLC_RTD.P$8@174.625,143.51 174.625,144.653 ; LLC_RTD.P$8@175.113,143.619 174.625,144.653
NTX: LLC_RTD.P$7 RTD.1 | length 18.5
  Top Layer w0.5: RTD.1@163.195,144.78 167.767,144.78 169.037,143.51 LLC_RTD.P$7@172.085,143.51 ; RTD.1@163.261,144.234 165.495,144.78 RTD.1@163.261,145.326 ; LLC_RTD.P$7@172.029,143.013 169.835,143.51 LLC_RTD.P$7@172.029,144.007
RXD_5V: LLC_Transmitter.P$7 Pressure_transmitter.6 | length 18.5
  Top Layer w0.5: Pressure_transmitter.6@163.195,163.449 165.735,163.449 167.005,164.719 LLC_Transmitter.P$7@172.085,164.719 ; Pressure_transmitter.6@163.261,162.903 165.495,163.449 Pressure_transmitter.6@163.261,163.995 ; LLC_Transmitter.P$7@172.029,164.222 169.835,164.719 LLC_Transmitter.P$7@172.029,165.216
TXD_5V: LLC_Transmitter.P$8 Pressure_transmitter.5 | length 26.6
  Top Layer w0.5: Pressure_transmitter.5@163.171,166.538 165.622,166.37 ; Pressure_transmitter.5@163.341,165.459 165.622,166.37 ; LLC_Transmitter.P$8@174.236,164.405 172.974,166.37 ; LLC_Transmitter.P$8@174.939,165.108 172.974,166.37 ; 165.622,166.37 Pressure_transmitter.5@163.195,165.989 163.576,166.37 172.974,166.37 ; 172.974,166.37 LLC_Transmitter.P$8@174.625,164.719 172.974,166.37
VDD: 
pads on no net: 7407_2.10 7407_2.11 7407_2.12 7407_2.13 7407_3.10 7407_3.11 7407_3.12 7407_3.13 7407_4.10 7407_4.11 7407_4.12 7407_4.13 7810.0 "5V to 3.3V.0" "CAN bus 1.5" "CAN bus 1.8" "CAN bus 2.5" "CAN bus 2.8" "Inductive IC(7407).8" "Inductive IC(7407).9" "Inductive IC(7407).10" "Inductive IC(7407).11" "Inductive IC(7407).12" "Inductive IC(7407).13" "RS232 out 1.1" "RS232 out 1.2" "RS232 out 1.4" "RS232 out 1.6" "RS232 out 1.7" "RS232 out 1.8" "RS232 out 1.10" "RS232 out 2.1" "RS232 out 2.2" "RS232 out 2.4" "RS232 out 2.6" "RS232 out 2.7" "RS232 out 2.8" "RS232 out 2.10" DC_motor1.2 DC_motor2.2 DC_MotorDriver1(7407).4 DC_MotorDriver1(7407).6 DC_MotorDriver1(7407).10 DC_MotorDriver1(7407).12 DSwitch2.7 DSwitch3.7 DSwitch.7 LLC_DCMotor1.P$1 LLC_DCMotor1.P$2 LLC_DCMotor1.P$4 LLC_DCMotor1.P$5 LLC_DCMotor1.P$9 LLC_DCMotor1.P$12 LLC_DCMotor2.P$2 LLC_DCMotor2.P$5 LLC_DCMotor2.P$6 LLC_DCMotor2.P$7 LLC_InductiveSensor.P$6 LLC_InductiveSensor.P$7 LLC_RTD.P$1 LLC_RTD.P$2 LLC_RTD.P$11 LLC_RTD.P$12 MAX232_1.11 MAX232_1.12 MAX232_1.13 MAX232_1.14 MAX232_2.11 MAX232_2.12 MAX232_2.13 MAX232_2.14

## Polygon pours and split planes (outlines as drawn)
GND on Top Layer "Bottom Layer-No Net" (solid, pour order 4): 157.226,256.794 335.407,256.794 335.407,56.642 335.153,56.388 334.899,56.642 157.226,56.642 157.226,256.794
GND on Bottom Layer "Bottom Layer-No Net" (solid, pour order 6): 157.226,256.794 334.899,256.794 335.153,256.54 335.661,256.032 335.661,56.515 157.353,56.515 157.226,56.388 157.48,56.642 157.48,256.54

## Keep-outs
Keep-Out Layer:
  lines w0.254: 157.226,84.328 157.226,256.794 335.407,256.794 335.407,56.388 157.226,56.388 157.226,89.281

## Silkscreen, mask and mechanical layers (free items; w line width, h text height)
Top Overlay:
  text "<-ground->" at 175.006,243.332 h0.8
  text "+24" at 330.835,238.633 h1
  text "+24" at 330.835,233.68 h1
  text "<-ground->" at 282.448,232.791 h0.8
  text "+24" at 330.835,228.854 h1
  text "+24" at 330.962,223.647 h1
  text "GND" at 158.877,209.042 h1
  text "+24" at 331.216,208.407 h1
  text "+24" at 158.75,206.502 h1
  text "+24" at 330.835,203.454 h1
  text "<-ground->" at 282.575,201.422 h0.8
  text "+24" at 331.089,198.374 h1
  text "GND" at 158.75,193.929 h1
  text "+24" at 330.835,193.167 h1
  text "+24" at 158.877,191.516 h1
  text "+24" at 330.962,177.8 h1
  text "GND" at 158.75,175.768 h1
  text "<-ground->" at 176.657,173.609 h0.8 r270
  text "+5" at 158.75,173.101 h1
  text "+24" at 330.581,172.847 h1
  text "<-ground->" at 282.321,171.577 h0.8
  text "+24" at 330.835,167.767 h1
  text "+24" at 330.581,162.56 h1
  text "<-ground->" at 176.53,152.527 h0.8 r270
  text "1" at 317.373,152.527 h1
  text "1" at 304.8,152.4 h1
  text "GND" at 165.227,151.892 h1
  text "GND" at 331.216,151.892 h1
  text "+10" at 331.216,149.733 h1
  text "+5" at 165.227,149.352 h1
  text "1" at 304.927,135.89 h1
  text "1" at 316.992,135.89 h1
  text "GND" at 330.708,134.493 h1
  text "<-ground->" at 238.125,133.604 h0.8 r270
  text "GND" at 160.909,132.588 h1.52
  text "+10" at 330.708,132.334 h1
  text "+" at 223.139,130.175 h1.52
  text "+" at 259.08,125.73 h1.52
  text "<-ground->" at 196.977,124.714 h0.8
  text "<-ground->" at 268.097,124.206 h0.8
  text "+" at 223.266,122.555 h1.52
  text "+" at 252.095,120.269 h1.52
  text "1" at 304.292,118.999 h1
  text "1" at 317.119,118.872 h1
  text "GND" at 331.089,117.856 h1
  text "+" at 223.139,115.824 h1.52
  text "+10" at 331.089,115.697 h1
  text "+" at 259.334,111.252 h1.52
  text "GND" at 161.036,110.363 h1.52
  text "+" at 218.186,108.204 h1.52
  text "<-ground->" at 196.977,107.696 h0.8
  text "+" at 259.588,104.394 h1.52
  text "GND" at 330.835,100.711 h1
  text "+5" at 330.835,98.552 h1
  text "+" at 254.254,97.282 h1.52
  text "+" at 218.313,97.155 h1.52
  text "<-ground->" at 289.56,90.678 h0.8
  text "GND" at 183.896,90.17 h1.52
  text "+" at 257.556,85.217 h1.52
  text "+" at 236.601,81.28 h1.52
  text "GND" at 330.835,81.153 h1
  text "+5" at 330.835,78.994 h1
  text "+" at 204.089,77.47 h1.52
  text "+" at 287.147,77.47 h1.52
  text "GND" at 184.023,72.771 h1.52
  text "+12" at 248.031,60.325 h1
  text "+24" at 238.125,60.198 h1
  text "GND" at 242.951,60.198 h1
  text "GND" at 252.984,60.198 h1
  text "GND" at 232.41,60.071 h1
  text "+5" at 258.191,59.817 h1

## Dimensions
328.93,193.802 to 328.93,180.848 on Mechanical 1
328.93,224.028 to 328.93,211.582 on Mechanical 1
328.93,241.808 to 335.407,256.794 on Mechanical 1
327.406,64.389 to 335.407,56.388 on Mechanical 1
327.406,64.389 to 335.407,56.388 on Mechanical 1
165.227,64.389 to 157.226,56.388 on Mechanical 1
165.227,64.389 to 157.226,56.388 on Mechanical 1
163.322,252.73 to 157.226,256.794 on Mechanical 1
163.322,252.73 to 157.226,256.794 on Mechanical 1
329.311,252.73 to 335.407,256.794 on Mechanical 1
329.311,252.73 to 335.407,256.794 on Mechanical 1
163.195,108.712 to 163.195,120.65 on Mechanical 1
163.195,144.78 to 163.195,130.81 on Mechanical 1
218.58,63.386 to 157.226,56.388 on Mechanical 1
218.58,63.386 to 233.566,67.45 on Mechanical 1
258.966,67.45 to 273.952,63.386 on Mechanical 1
258.966,67.45 to 335.407,56.388 on Mechanical 1
233.566,67.45 to 157.226,56.388 on Mechanical 1
258.966,67.45 to 335.407,56.388 on Mechanical 1
328.93,93.726 to 328.93,81.788 on Mechanical 1
328.93,101.346 to 328.93,113.284 on Mechanical 1
163.195,152.4 to 163.195,163.449 on Mechanical 1
163.195,176.149 to 163.195,189.23 on Mechanical 1
163.195,209.423 to 163.195,228.473 on Mechanical 1
157.226,84.328 to 335.407,56.388 on Mechanical 1
335.407,256.794 to 335.407,56.388 on Mechanical 1
163.195,176.149 to 172.085,174.879 on Mechanical 1
163.195,204.343 to 163.195,194.31 on Mechanical 1
213.487,150.749 to 266.827,150.749 on Mechanical 1
328.93,147.32 to 328.93,135.382 on Mechanical 1
328.93,130.302 to 328.93,118.364 on Mechanical 1
216.027,211.709 to 157.226,256.794 on Mechanical 1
